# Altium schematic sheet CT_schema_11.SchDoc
size 382 x 278 mm
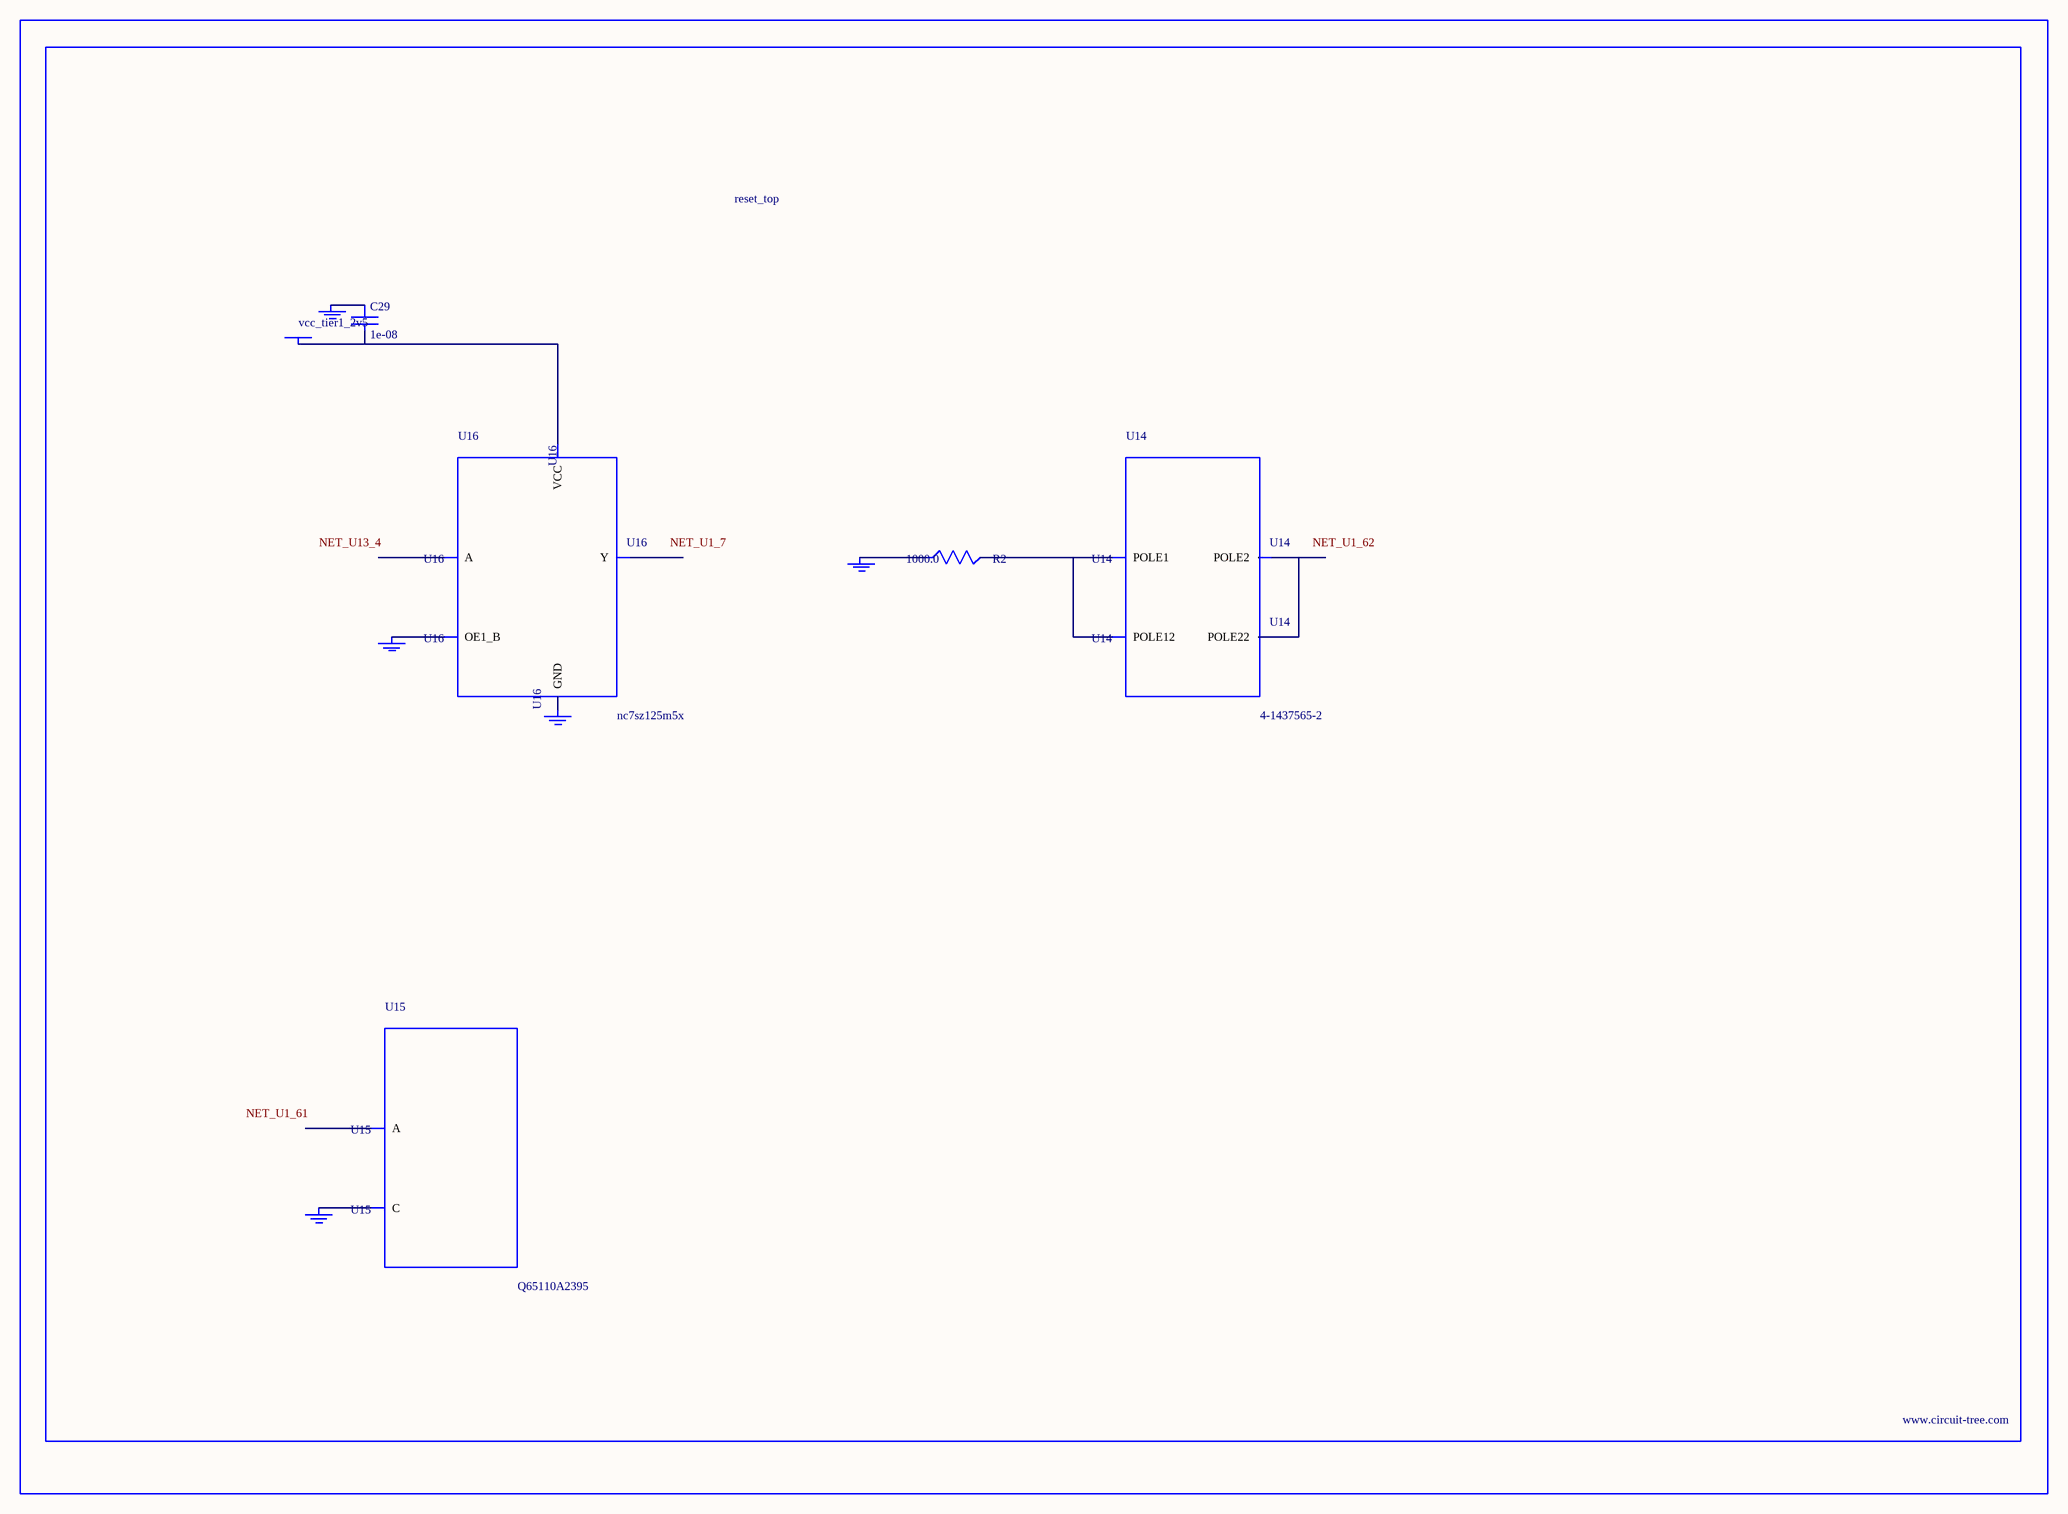
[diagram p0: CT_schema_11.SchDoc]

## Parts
BORDER10  (no value)
C29  1e-08  [C0402]
GND_INSTANCE_10_0  (no value)
GND_INSTANCE_10_1  (no value)
GND_INSTANCE_10_2  (no value)
GND_INSTANCE_10_3  (no value)
GND_INSTANCE_10_4  (no value)
POWER_INSTANCE_10_0  vcc_tier1_2v5
R2  1000.0  [R0603]
U14  4-1437565-2  [SW_4-1437565-2]
U15  Q65110A2395  [LGM67K-G1J2-24-Z]
U16  nc7sz125m5x  [NC7SZ125M5X]

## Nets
NetC29_1: C29.1 GND_INSTANCE_10_2.0(GND)
NetC29_2: C29.2 POWER_INSTANCE_10_0.0(PWR) U16.5(VCC)
NetGND_INSTANCE_10_0_0: GND_INSTANCE_10_0.0(GND) R2.1
NetGND_INSTANCE_10_1_0: GND_INSTANCE_10_1.0(GND) U15.C
NetGND_INSTANCE_10_3_0: GND_INSTANCE_10_3.0(GND) U16.1(OE1_B)
NetGND_INSTANCE_10_4_0: GND_INSTANCE_10_4.0(GND) U16.3(GND)
NetR2_2: R2.2 U14.1(POLE1) U14.2(POLE12)
NetU14_3: U14.3(POLE2) U14.4(POLE22)

Not connected (* = marked no-connect by the designer): U15 A; U16 2(A) 4(Y)

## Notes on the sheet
- Labels drawn without touching a wire or pin: NET_U1_7, NET_U1_61, NET_U1_62, NET_U13_4

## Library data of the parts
BORDER10 = BORDER_PAGE10
C29 = C0402C103K3RAC
GND_INSTANCE_10_0-GND_INSTANCE_10_4 = GND
POWER_INSTANCE_10_0 = PWR
R2 = RC0603JR-071KL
